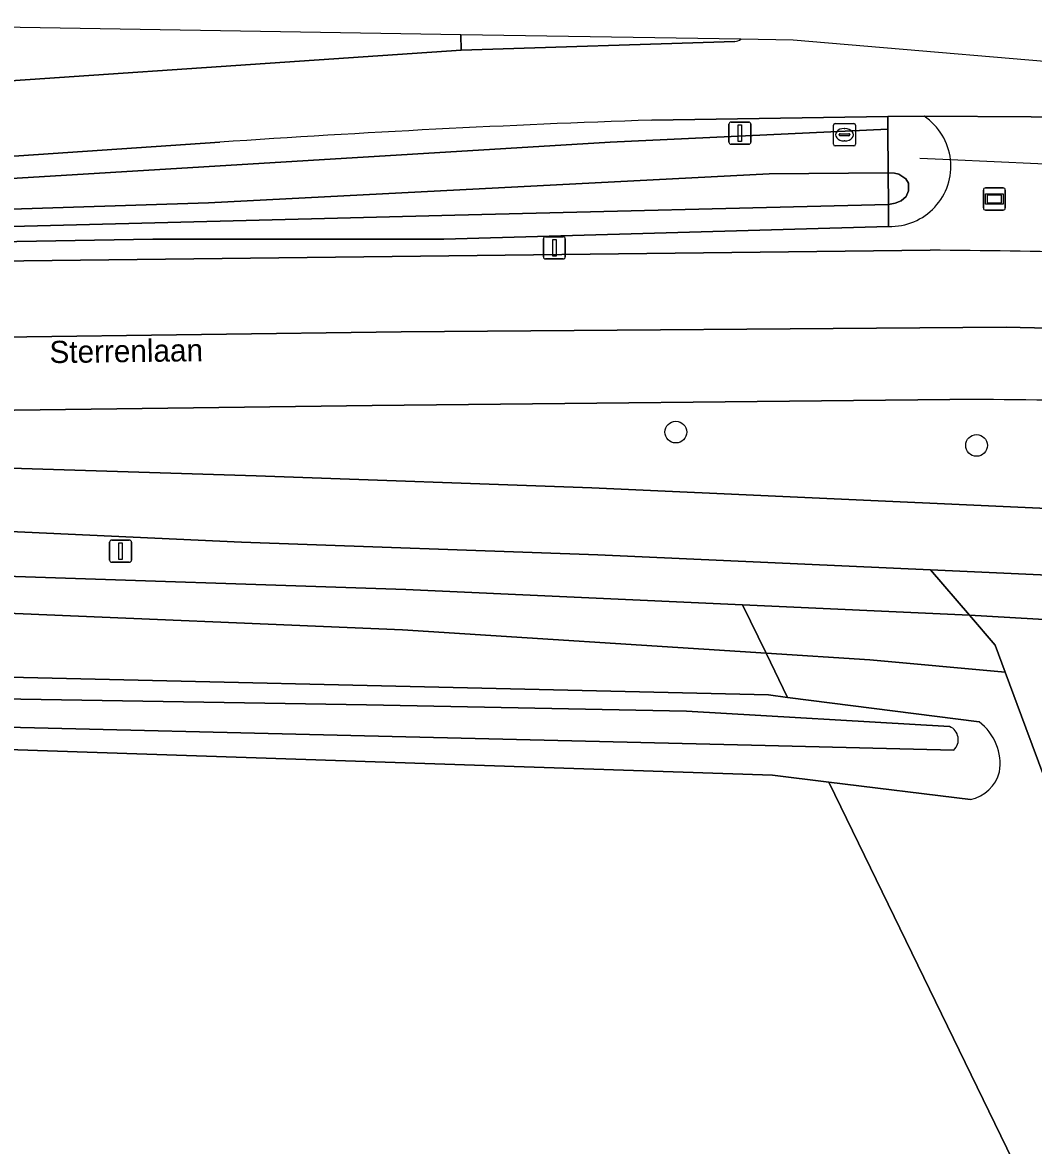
# Model space of a CAD drawing. Extents: x 162788 to 163838, y 385791 to 386523.
# Drawn here: x 163367.1 to 163412.6, y 386471.6 to 386522.2 of the extents above; entities that cross this region are included whole.
import ezdxf

# ---------------------------------------------------------------- set-up
doc = ezdxf.new("R2010")
doc.units = 0
for name, color, linetype in [('IMGEO_Berm_groen', 7, 'Continuous'), ('IMGEO_Boom', 7, 'Continuous'), ('IMGEO_Duiker', 7, 'Continuous'), ('IMGEO_Fietspad_gesloten', 7, 'Continuous'), ('IMGEO_Groenvoorziening', 7, 'Continuous'), ('IMGEO_Lichtmast', 7, 'Continuous'), ('IMGEO_Loofbos', 7, 'Continuous'), ('IMGEO_Oever', 7, 'Continuous'), ('IMGEO_Openbare_ruimte_label', 7, 'Continuous'), ('IMGEO_OVBaan_gesloten', 7, 'Continuous'), ('IMGEO_Reclamebord', 7, 'Continuous'), ('IMGEO_Rijbaan_regionaal_gesloten', 7, 'Continuous'), ('IMGEO_Rioolput', 7, 'Continuous'), ('IMGEO_Verkeersbordpaal', 7, 'Continuous'), ('IMGEO_Verkeerseiland_gesloten', 7, 'Continuous'), ('IMGEO_Waterloop', 7, 'Continuous')]:
    doc.layers.add(name, color=color, linetype=linetype)

msp = doc.modelspace()

# ---------------------------------------------------------------- linework, layer by layer
at = {"layer": 'IMGEO_Berm_groen'}
for points in [[(163289.038, 386517.264), (163307.015, 386517.467), (163307.031, 386517.639), (163307.622, 386517.691), (163307.634, 386517.464), (163318.563, 386517.629), (163328.642, 386517.781), (163343.445, 386518.239), (163358.569, 386518.995), (163386.835, 386520.916), (163386.815, 386521.618), (163353.405, 386522.168)], [(163352.723, 386514.303), (163393.536, 386516.774), (163406.048, 386517.363), (163406.043, 386517.934), (163395.419, 386517.772)], [(163417.332, 386517.881), (163407.685, 386517.941)], [(163375.96, 386516.773), (163356.293, 386515.445)], [(163334.308, 386514.542), (163323.582, 386514.381), (163278.501, 386513.704), (163278.578, 386510.168), (163320.348, 386510.874), (163328.845, 386510.975), (163407.961, 386511.911)], [(163406.086, 386512.983), (163386.044, 386512.404), (163372.937, 386512.412), (163341.46, 386511.859), (163327.669, 386511.736), (163306.981, 386511.551)], [(163408.845, 386505.184), (163382.823, 386504.918), (163339.084, 386504.348), (163313.816, 386504.019), (163312.779, 386502.838), (163322.556, 386503.048), (163336.698, 386502.829), (163341.58, 386502.733), (163354.063, 386502.487), (163377.597, 386501.753), (163392.717, 386501.21), (163422.157, 386499.862), (163437.07, 386498.936), (163447.684, 386498.2), (163451.775, 386497.917), (163476.422, 386495.841), (163497.382, 386493.95), (163513.463, 386492.329), (163543.158, 386489.078), (163569.498, 386486.424)]]:
    msp.add_lwpolyline(points, dxfattribs=at)
for centre, radius, start, end in [((163414.785, 385950.543), 567.559, 91.95537, 93.92246), ((163406.176, 386515.687), 2.712, 6.4256, 56.1908), ((163406.179, 386515.69), 2.708, 268.0242, 6.3848), ((163405.171, 386125.878), 386.043, 87.45061, 89.58585), ((163408.789, 386200.589), 304.595, 87.04502, 89.98942)]:
    msp.add_arc(centre, radius, start, end, dxfattribs=at)
at = {"layer": 'IMGEO_Boom'}
for centre in [(163396.5, 386503.718), (163410.045, 386503.118)]:
    msp.add_circle(centre, 0.489, dxfattribs=at)
at = {"layer": 'IMGEO_Duiker'}
msp.add_lwpolyline([(163407.484, 386516.051), (163408.871, 386515.991), (163412.81, 386515.819), (163421.369, 386515.254), (163422.253, 386515.196)], dxfattribs=at)
at = {"layer": 'IMGEO_Fietspad_gesloten'}
for points in [[(163447.684, 386498.2), (163437.07, 386498.936), (163422.157, 386499.862), (163392.717, 386501.21), (163377.597, 386501.753), (163354.063, 386502.487), (163341.58, 386502.733), (163336.698, 386502.829), (163322.556, 386503.048), (163312.779, 386502.838), (163305.812, 386502.688), (163285.169, 386502.244), (163273.946, 386502.195)], [(163274.146, 386499.134), (163285.095, 386499.165), (163336.276, 386500.228), (163345.782, 386500.013), (163353.5, 386499.838), (163376.942, 386498.76), (163392.983, 386498.182), (163407.967, 386497.506), (163416.565, 386497.119), (163421.921, 386496.877), (163436.207, 386495.962), (163447.558, 386495.135), (163447.684, 386498.2)]]:
    msp.add_lwpolyline(points, dxfattribs=at)
at = {"layer": 'IMGEO_Groenvoorziening'}
for points in [[(163213.396, 386495.29), (163216.052, 386495.316), (163240.009, 386495.549), (163267.522, 386495.587), (163266.803, 386496.874), (163270.103, 386497.032), (163273.491, 386497.298), (163276.018, 386497.562), (163279.712, 386498), (163282.042, 386498.022), (163308.809, 386497.509), (163318.366, 386497.664), (163343.676, 386497.629), (163349.624, 386497.527), (163365.389, 386497.256), (163384.342, 386496.626), (163399.5, 386495.937), (163409.721, 386495.473), (163407.967, 386497.506), (163392.983, 386498.182), (163376.942, 386498.76), (163353.5, 386499.838)], [(163423.585, 386464.146), (163414.511, 386483.948), (163414.652, 386483.994), (163413.65, 386486.689), (163412.272, 386490.396), (163411.34, 386492.903), (163405.235, 386493.454), (163400.563, 386493.754), (163401.529, 386491.768), (163410.163, 386490.665)], [(163409.774, 386487.164), (163403.388, 386487.947), (163421.295, 386451.142), (163442.645, 386407.261), (163447.662, 386411.875), (163448.879, 386413.338), (163450.146, 386416.054), (163446.214, 386422.129), (163423.585, 386464.146)]]:
    msp.add_lwpolyline(points, dxfattribs=at)
for points in [[(163282.042, 386498.022), (163287.556, 386495.542), (163308.768, 386495.17), (163343.996, 386496.009), (163352.211, 386495.853), (163365.669, 386495.597), (163384.182, 386494.806), (163400.563, 386493.754), (163399.5, 386495.937), (163384.342, 386496.626), (163365.389, 386497.256), (163349.624, 386497.527), (163343.676, 386497.629), (163318.366, 386497.664), (163308.809, 386497.509)], [(163407.967, 386497.506), (163409.721, 386495.473), (163416.729, 386495.064), (163416.565, 386497.119)], [(163365.669, 386495.597), (163352.211, 386495.853), (163343.996, 386496.009), (163308.768, 386495.17), (163287.556, 386495.542), (163342.835, 386493.227), (163343.577, 386493.21), (163356.77, 386492.902), (163400.676, 386491.877), (163401.529, 386491.768), (163400.563, 386493.754), (163384.182, 386494.806)], [(163411.34, 386492.903), (163410.887, 386494.12), (163409.721, 386495.473), (163399.5, 386495.937), (163400.563, 386493.754), (163405.235, 386493.454)], [(163418.278, 386486.121), (163417.443, 386489.736), (163416.941, 386492.397), (163416.729, 386495.064), (163409.721, 386495.473), (163410.887, 386494.12), (163411.34, 386492.903), (163412.272, 386490.396), (163413.65, 386486.689), (163414.652, 386483.994), (163418.487, 386485.231)]]:
    msp.add_lwpolyline(points, close=True, dxfattribs=at)
for centre, radius, start, end in [((163408.719, 386488.761), 2.389, 351.4721, 52.8203), ((163409.392, 386488.876), 1.754, 282.5903, 344.4905)]:
    msp.add_arc(centre, radius, start, end, dxfattribs=at)
at = {"layer": 'IMGEO_Lichtmast'}
for p, q in [((163390.633, 386512.517), (163391.423, 386512.517)), ((163391.423, 386512.517), (163390.633, 386512.517)), ((163390.533, 386511.617), (163390.533, 386512.417)), ((163390.533, 386512.417), (163390.533, 386511.617)), ((163391.523, 386512.417), (163391.523, 386511.617)), ((163391.523, 386511.617), (163391.523, 386512.417)), ((163391.423, 386511.517), (163390.633, 386511.517)), ((163390.633, 386511.517), (163391.423, 386511.517))]:
    msp.add_line(p, q, dxfattribs=at)
msp.add_lwpolyline([(163390.953, 386512.392), (163391.103, 386512.392), (163391.103, 386511.642), (163390.953, 386511.642), (163390.953, 386512.392)], dxfattribs=at)
for centre, start, end in [((163390.633, 386512.417), 90, 180), ((163390.633, 386512.417), 90, 180), ((163391.423, 386512.417), 0, 90), ((163391.423, 386512.417), 360, 90), ((163390.633, 386511.617), 180, 270), ((163390.633, 386511.617), 180, 270), ((163391.423, 386511.617), 270, 0), ((163391.423, 386511.617), 270, 0)]:
    msp.add_arc(centre, 0.1, start, end, dxfattribs=at)
at = {"layer": 'IMGEO_Loofbos'}
msp.add_lwpolyline([(163442.645, 386407.261), (163421.295, 386451.142), (163403.388, 386487.947), (163400.855, 386488.258), (163361.92, 386489.569), (163343.653, 386490.184), (163343.048, 386490.514), (163342.818, 386490.69), (163342.57, 386490.879), (163342.345, 386491.332), (163342.457, 386491.84)], dxfattribs=at)
at = {"layer": 'IMGEO_Oever'}
for points in [[(163406.065, 386515.398), (163406.048, 386517.363), (163393.536, 386516.774), (163352.723, 386514.303)], [(163306.981, 386511.551), (163327.669, 386511.736), (163341.46, 386511.859), (163372.937, 386512.412), (163386.044, 386512.404), (163406.086, 386512.983), (163406.077, 386513.965), (163386.544, 386513.487), (163364.791, 386512.929), (163324.333, 386511.829), (163307.737, 386511.865), (163307.619, 386511.919), (163307.501, 386512.021), (163307.469, 386512.101), (163307.472, 386512.258), (163307.511, 386512.339), (163307.596, 386512.429), (163307.699, 386512.508), (163336.621, 386512.796), (163375.455, 386514.037), (163400.711, 386515.351), (163406.065, 386515.398)], [(163410.163, 386490.665), (163401.529, 386491.768), (163400.676, 386491.877), (163356.77, 386492.902), (163343.577, 386493.21)], [(163342.457, 386491.84), (163342.345, 386491.332), (163342.57, 386490.879), (163342.818, 386490.69), (163343.048, 386490.514), (163343.653, 386490.184), (163361.92, 386489.569), (163400.855, 386488.258), (163403.388, 386487.947), (163409.774, 386487.164)], [(163344.085, 386492.067), (163382.561, 386491.434), (163396.982, 386491.142), (163408.832, 386490.453)], [(163409.018, 386489.394), (163400.518, 386489.6), (163383.729, 386490.005), (163344.037, 386490.964)]]:
    msp.add_lwpolyline(points, dxfattribs=at)
for centre, radius, start, end in [((163408.582, 386489.863), 0.641, 312.9006, 67.0227), ((163408.719, 386488.761), 2.389, 351.4721, 52.8203), ((163409.392, 386488.876), 1.754, 282.5903, 344.4905)]:
    msp.add_arc(centre, radius, start, end, dxfattribs=at)
at = {"layer": 'IMGEO_OVBaan_gesloten'}
for points in [[(163407.961, 386511.911), (163328.845, 386510.975), (163320.348, 386510.874), (163278.578, 386510.168), (163278.085, 386510.16), (163278.133, 386506.832), (163330.158, 386507.517), (163384.122, 386508.228), (163411.373, 386508.445), (163426.029, 386508.092), (163448.04, 386506.684), (163448.179, 386509.931), (163444.84, 386510.182)], [(163447.898, 386503.378), (163448.04, 386506.684), (163426.029, 386508.092), (163411.373, 386508.445), (163384.122, 386508.228), (163330.158, 386507.517), (163278.133, 386506.832)], [(163278.133, 386506.832), (163278.18, 386503.527), (163304.582, 386503.895), (163313.816, 386504.019), (163339.084, 386504.348), (163382.823, 386504.918), (163408.845, 386505.184)]]:
    msp.add_lwpolyline(points, dxfattribs=at)
for centre, radius, start, end in [((163405.171, 386125.878), 386.043, 87.45061, 89.58585), ((163408.789, 386200.589), 304.595, 87.04502, 89.98942)]:
    msp.add_arc(centre, radius, start, end, dxfattribs=at)
at = {"layer": 'IMGEO_Reclamebord'}
for p, q in [((163410.351, 386513.814), (163410.351, 386514.614)), ((163410.351, 386514.614), (163410.351, 386513.814)), ((163410.451, 386514.714), (163411.241, 386514.714)), ((163411.241, 386514.714), (163410.451, 386514.714)), ((163411.341, 386514.614), (163411.341, 386513.814)), ((163411.341, 386513.814), (163411.341, 386514.614)), ((163411.241, 386513.714), (163410.451, 386513.714)), ((163410.451, 386513.714), (163411.241, 386513.714))]:
    msp.add_line(p, q, dxfattribs=at)
for points in [[(163410.452, 386514.446), (163411.24, 386514.446), (163411.24, 386513.982), (163410.452, 386513.982), (163410.452, 386514.446)], [(163410.517, 386514.381), (163410.517, 386514.047), (163411.175, 386514.047), (163411.175, 386514.381), (163410.517, 386514.381)]]:
    msp.add_lwpolyline(points, dxfattribs=at)
for centre, start, end in [((163410.451, 386514.614), 90, 180), ((163410.451, 386514.614), 90, 180), ((163411.241, 386514.614), 0, 90), ((163411.241, 386514.614), 360, 90), ((163410.451, 386513.814), 180, 270), ((163410.451, 386513.814), 180, 270), ((163411.241, 386513.814), 270, 0), ((163411.241, 386513.814), 270, 0)]:
    msp.add_arc(centre, 0.1, start, end, dxfattribs=at)
at = {"layer": 'IMGEO_Rijbaan_regionaal_gesloten'}
for points in [[(163399.159, 386521.317), (163386.835, 386520.916), (163358.569, 386518.995), (163343.445, 386518.239), (163328.642, 386517.781), (163318.563, 386517.629), (163307.634, 386517.464), (163307.622, 386517.691), (163307.031, 386517.639), (163307.015, 386517.467), (163289.038, 386517.264)], [(163448.498, 386517.406), (163401.783, 386521.372), (163399.425, 386521.411)], [(163395.419, 386517.772), (163406.043, 386517.934), (163407.685, 386517.941), (163417.332, 386517.881)], [(163356.293, 386515.445), (163375.96, 386516.773)]]:
    msp.add_lwpolyline(points, dxfattribs=at)
for centre, radius, start, end in [((163399.131, 386521.818), 0.502, 273.1628, 305.7488), ((163414.785, 385950.543), 567.559, 91.95537, 93.92246)]:
    msp.add_arc(centre, radius, start, end, dxfattribs=at)
at = {"layer": 'IMGEO_Rioolput'}
for p, q in [((163403.597, 386516.685), (163403.597, 386517.537)), ((163403.672, 386517.611), (163404.524, 386517.611)), ((163404.598, 386517.537), (163404.598, 386516.685)), ((163403.856, 386517.105), (163403.856, 386517.117)), ((163404.294, 386517.068), (163403.896, 386517.068)), ((163403.899, 386517.154), (163404.297, 386517.154)), ((163404.085, 386517.391), (163404.11, 386517.391)), ((163404.34, 386517.117), (163404.34, 386517.105)), ((163404.524, 386516.611), (163403.672, 386516.611)), ((163404.108, 386516.831), (163404.083, 386516.831))]:
    msp.add_line(p, q, dxfattribs=at)
for points in [[(163403.597, 386516.685), (163403.597, 386517.537)], [(163403.672, 386517.611), (163404.524, 386517.611)], [(163404.598, 386517.537), (163404.598, 386516.685)], [(163404.524, 386516.611), (163403.672, 386516.611)]]:
    msp.add_lwpolyline(points, dxfattribs=at)
for centre, radius, start, end in [((163403.674, 386517.535), 0.0765, 91.552, 178.448), ((163403.674, 386517.535), 0.0765, 91.552, 178.448), ((163404.522, 386517.535), 0.0765, 1.552, 88.448), ((163404.522, 386517.535), 0.0765, 1.552, 88.448), ((163403.896, 386517.114), 0.0403, 85.8775, 175.7526), ((163403.893, 386517.104), 0.0366, 178.938, 274.7102), ((163404.297, 386517.111), 0.043, 264.8664, 352.4533), ((163404.301, 386517.116), 0.0386, 1.7309, 96.639), ((163403.674, 386516.687), 0.0765, 181.552, 268.448), ((163403.674, 386516.687), 0.0765, 181.552, 268.448), ((163404.522, 386516.687), 0.0765, 271.552, 358.448), ((163404.522, 386516.687), 0.0765, 271.552, 358.448)]:
    msp.add_arc(centre, radius, start, end, dxfattribs=at)
for centre, major_axis, ratio, start_param, end_param in [((163404.084, 386517.111), (-0.387, 0.002), 0.722429, 4.712389, 7.853982), ((163404.109, 386517.111), (-0.39, 0.002), 0.717154, 1.570796, 4.712389)]:
    msp.add_ellipse(centre, major_axis=major_axis, ratio=ratio, start_param=start_param, end_param=end_param, dxfattribs=at)
at = {"layer": 'IMGEO_Verkeersbordpaal'}
for p, q in [((163398.892, 386516.783), (163398.892, 386517.583)), ((163398.892, 386517.583), (163398.892, 386516.783)), ((163398.992, 386517.683), (163399.782, 386517.683)), ((163399.782, 386517.683), (163398.992, 386517.683)), ((163399.882, 386517.583), (163399.882, 386516.783)), ((163399.882, 386516.783), (163399.882, 386517.583)), ((163399.782, 386516.683), (163398.992, 386516.683)), ((163398.992, 386516.683), (163399.782, 386516.683)), ((163371.095, 386498.851), (163371.885, 386498.851)), ((163371.885, 386498.851), (163371.095, 386498.851)), ((163370.995, 386497.951), (163370.995, 386498.751)), ((163370.995, 386498.751), (163370.995, 386497.951)), ((163371.985, 386498.751), (163371.985, 386497.951)), ((163371.985, 386497.951), (163371.985, 386498.751)), ((163371.885, 386497.851), (163371.095, 386497.851)), ((163371.095, 386497.851), (163371.885, 386497.851))]:
    msp.add_line(p, q, dxfattribs=at)
for points in [[(163399.312, 386517.558), (163399.462, 386517.558), (163399.462, 386516.808), (163399.312, 386516.808), (163399.312, 386517.558)], [(163371.415, 386498.726), (163371.565, 386498.726), (163371.565, 386497.976), (163371.415, 386497.976), (163371.415, 386498.726)]]:
    msp.add_lwpolyline(points, dxfattribs=at)
for centre, start, end in [((163398.992, 386517.583), 90, 180), ((163398.992, 386517.583), 90, 180), ((163399.782, 386517.583), 0, 90), ((163399.782, 386517.583), 360, 90), ((163398.992, 386516.783), 180, 270), ((163398.992, 386516.783), 180, 270), ((163399.782, 386516.783), 270, 0), ((163399.782, 386516.783), 270, 0), ((163371.095, 386498.751), 90, 180), ((163371.095, 386498.751), 90, 180), ((163371.885, 386498.751), 0, 90), ((163371.885, 386498.751), 360, 90), ((163371.095, 386497.951), 180, 270), ((163371.095, 386497.951), 180, 270), ((163371.885, 386497.951), 270, 0), ((163371.885, 386497.951), 270, 0)]:
    msp.add_arc(centre, 0.1, start, end, dxfattribs=at)
at = {"layer": 'IMGEO_Verkeerseiland_gesloten'}
for points in [[(163399.425, 386521.411), (163386.815, 386521.618), (163386.835, 386520.916), (163399.159, 386521.317)], [(163407.685, 386517.941), (163406.043, 386517.934), (163406.048, 386517.363), (163406.065, 386515.398), (163406.351, 386515.384), (163406.544, 386515.34), (163406.863, 386515.128), (163406.979, 386514.934), (163406.986, 386514.577), (163406.868, 386514.325), (163406.647, 386514.14), (163406.376, 386514.035), (163406.077, 386513.965), (163406.086, 386512.983)]]:
    msp.add_lwpolyline(points, dxfattribs=at)
msp.add_lwpolyline([(163406.065, 386515.398), (163406.077, 386513.965), (163406.376, 386514.035), (163406.647, 386514.14), (163406.868, 386514.325), (163406.986, 386514.577), (163406.979, 386514.934), (163406.863, 386515.128), (163406.544, 386515.34), (163406.351, 386515.384)], close=True, dxfattribs=at)
for centre, radius, start, end in [((163399.131, 386521.818), 0.502, 273.1628, 305.7488), ((163406.176, 386515.687), 2.712, 6.4256, 56.1908), ((163406.179, 386515.69), 2.708, 268.0242, 6.3848)]:
    msp.add_arc(centre, radius, start, end, dxfattribs=at)
at = {"layer": 'IMGEO_Waterloop'}
msp.add_lwpolyline([(163406.077, 386513.965), (163406.065, 386515.398), (163400.711, 386515.351), (163375.455, 386514.037), (163336.621, 386512.796), (163307.699, 386512.508), (163307.596, 386512.429), (163307.511, 386512.339), (163307.472, 386512.258), (163307.469, 386512.101), (163307.501, 386512.021), (163307.619, 386511.919), (163307.737, 386511.865), (163324.333, 386511.829), (163364.791, 386512.929), (163386.544, 386513.487)], close=True, dxfattribs=at)
for points in [[(163408.832, 386490.453), (163396.982, 386491.142), (163382.561, 386491.434), (163344.085, 386492.067)], [(163344.037, 386490.964), (163383.729, 386490.005), (163400.518, 386489.6), (163409.018, 386489.394)]]:
    msp.add_lwpolyline(points, dxfattribs=at)
msp.add_arc((163408.582, 386489.863), 0.641, 312.9006, 67.0227, dxfattribs=at)

# ---------------------------------------------------------------- texts
at = {"layer": 'IMGEO_Openbare_ruimte_label'}
msp.add_text('Sterrenlaan', height=1, rotation=0.7448, dxfattribs=at).set_placement((163368.296, 386506.822))

doc.saveas('drawing.dxf')
